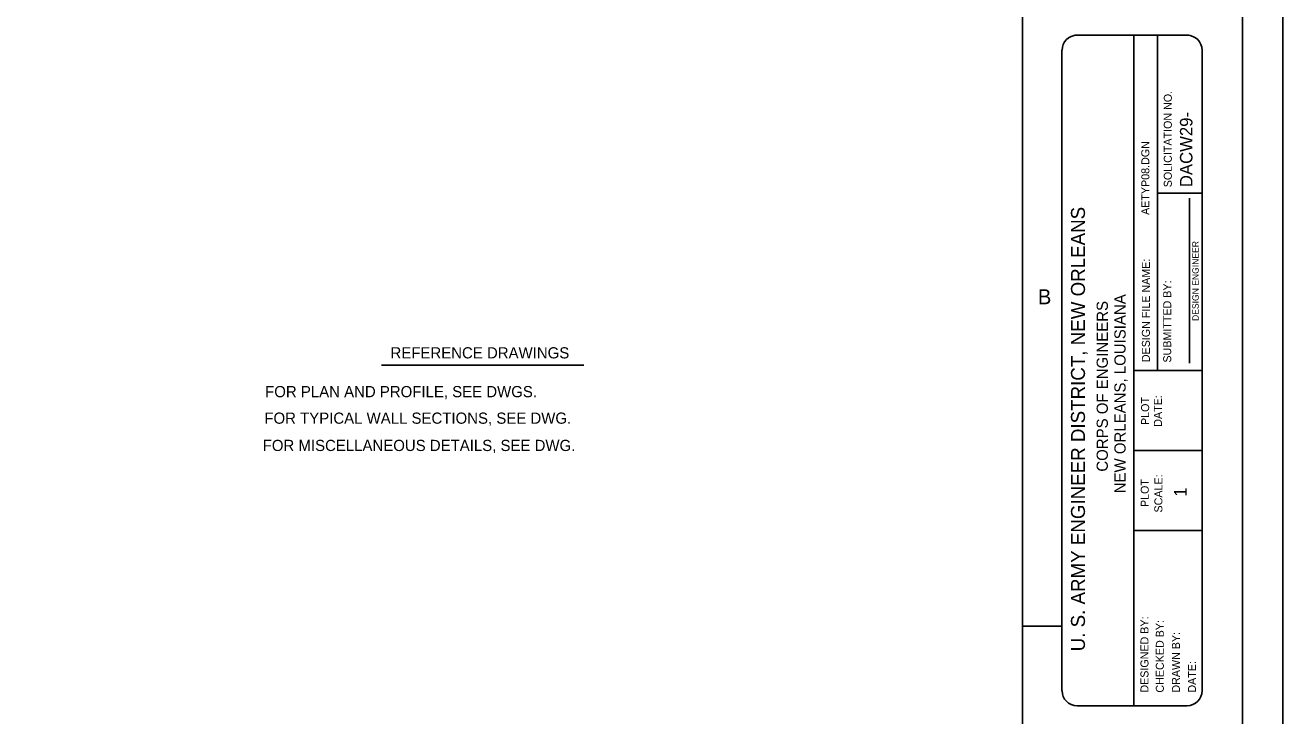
# Model space of a CAD drawing. Extents: x 44743.44 to 44747.1, y 44738.46 to 44741.29.
# Drawn here: x 44745.795 to 44747.105, y 44739.093 to 44739.812 of the extents above; entities that cross this region are included whole.
import ezdxf

# ---------------------------------------------------------------- set-up
doc = ezdxf.new("R2010")
doc.units = 0
for name, color, linetype in [('Level 1', 7, 'Continuous'), ('Level 10', 7, 'Continuous'), ('Level 2', 7, 'Continuous'), ('Level 7', 7, 'Continuous'), ('Level 9', 7, 'Continuous'), ('S-ANNO-TEXT', 7, 'Continuous')]:
    doc.layers.add(name, color=color, linetype=linetype)

msp = doc.modelspace()

# ---------------------------------------------------------------- linework, layer by layer
at = {"layer": 'Level 1'}
for p, q in [((44747.0067, 44739.8018), (44746.8877, 44739.8018)), ((44746.9497, 44739.8018), (44746.9497, 44739.1038))]:
    msp.add_line(p, q, dxfattribs=at)
msp.add_lwpolyline([(44743.438, 44741.2918), (44747.1047, 44741.2918), (44747.1047, 44738.4578), (44743.438, 44738.4578)], close=True, dxfattribs=at)
for points in [[(44747.0051, 44739.8018), (44746.8904, 44739.8018)], [(44746.8747, 44739.1195), (44746.8747, 44739.7862)], [(44747.0207, 44739.1195), (44747.0207, 44739.7862)], [(44746.8904, 44739.1038), (44747.0051, 44739.1038)]]:
    msp.add_lwpolyline(points, dxfattribs=at)
for centre, start, end in [((44746.8904, 44739.7862), 90, 180), ((44747.0051, 44739.7862), 0, 90), ((44746.8904, 44739.1195), 180, 270), ((44747.0051, 44739.1195), 270, 0)]:
    msp.add_arc(centre, 0.0156, start, end, dxfattribs=at)
at = {"layer": 'Level 10'}
msp.add_line((44746.8337, 44739.1868), (44746.8747, 44739.1868), dxfattribs=at)
at = {"layer": 'Level 2'}
for p, q in [((44746.9743, 44739.8018), (44746.9743, 44739.4528)), ((44747.0207, 44739.6375), (44746.9743, 44739.6375)), ((44747.0077, 44739.4604), (44747.0077, 44739.6322)), ((44747.0207, 44739.4528), (44746.9497, 44739.4528)), ((44747.0207, 44739.3695), (44746.9497, 44739.3695)), ((44747.0207, 44739.2862), (44746.9497, 44739.2862))]:
    msp.add_line(p, q, dxfattribs=at)
at = {"layer": 'Level 7'}
msp.add_line((44746.1662, 44739.4584), (44746.3768, 44739.4584), dxfattribs=at)
at = {"layer": 'Level 9'}
msp.add_line((44747.0627, 44738.4998), (44747.0627, 44741.2498), dxfattribs=at)
msp.add_lwpolyline([(44746.8337, 44738.4998), (44746.8337, 44741.2498)], dxfattribs=at)

# ---------------------------------------------------------------- texts
at = {"layer": 'Level 1'}
for s, height, p in [('SOLICITATION NO.', 0.008334, (44746.9891, 44739.6436)), ('AETYP08.DGN', 0.008333, (44746.9657, 44739.6148)), ('U. S. ARMY ENGINEER DISTRICT, NEW ORLEANS', 0.014583, (44746.8987, 44739.1605)), ('DESIGN ENGINEER', 0.006666, (44747.0171, 44739.5044)), ('DESIGN FILE NAME:', 0.008334, (44746.9663, 44739.4615)), ('SUBMITTED BY:', 0.008334, (44746.9885, 44739.4611)), ('PLOT', 0.00833, (44746.9655, 44739.3961)), ('DATE:', 0.00833, (44746.9788, 44739.3943)), ('SCALE:', 0.00833, (44746.9793, 44739.305)), ('PLOT', 0.00833, (44746.9651, 44739.3107)), ('DESIGNED BY:', 0.008334, (44746.9648, 44739.1175)), ('CHECKED BY:', 0.008334, (44746.9808, 44739.1175)), ('DRAWN BY:', 0.00833, (44746.9976, 44739.1175)), ('DATE:', 0.00833, (44747.0143, 44739.1175))]:
    msp.add_text(s, height=height, rotation=90, dxfattribs=at).set_placement(p)
msp.add_text('B', height=0.0156, dxfattribs=at).set_placement((44746.8497, 44739.5218))
at = {"layer": 'Level 7'}
for s, height, p in [('DACW29-', 0.013, (44747.0106, 44739.6437)), ('NEW ORLEANS, LOUISIANA', 0.011667, (44746.941, 44739.325)), ('CORPS OF ENGINEERS', 0.011667, (44746.9225, 44739.3475)), ('1', 0.013, (44747.0045, 44739.3214))]:
    msp.add_text(s, height=height, rotation=90, dxfattribs=at).set_placement(p)
at = {"layer": 'S-ANNO-TEXT'}
for s, p in [('REFERENCE DRAWINGS', (44746.1755, 44739.4654)), ('FOR PLAN AND PROFILE, SEE DWGS.', (44746.0449, 44739.425)), ('FOR TYPICAL WALL SECTIONS, SEE DWG.', (44746.0441, 44739.3974)), ('FOR MISCELLANEOUS DETAILS, SEE DWG.', (44746.0424, 44739.369))]:
    msp.add_text(s, height=0.011653, dxfattribs=at).set_placement(p)

doc.saveas('drawing.dxf')
